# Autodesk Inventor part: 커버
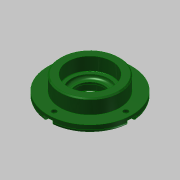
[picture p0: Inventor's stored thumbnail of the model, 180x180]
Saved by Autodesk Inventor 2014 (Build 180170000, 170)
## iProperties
Company: 한국ATC센터
Created: 2016-04
Part Number: 커버
Document SubType Name: Modeling
Designer: mdu
Density: 7.86 g/cm^3
Mass: 351.567 g
Surface Area: 161.165 cm^2
Volume: 44.7286 cm^3
Material: 강철, 연강
Appearance: 진녹색
Author: mdu
Revision Number: 1
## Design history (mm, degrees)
sketch "스케치1"
  geometry: C1 r 38 at (0, 0); 1 further point
  constraints: 1 centre point, 1 coincident
  dimensions: "d0" = 76 diameter of C1
extrude "돌출1" new body sketch "스케치1" distance "d1" = 7; taper "d2" = 0 deg
sketch "스케치2"
  geometry: C1 r 27 at (0, 0); 1 further point
  constraints: 1 centre point, 1 coincident
  dimensions: "d3" = 54 diameter of C1
extrude "돌출2" join sketch "스케치2" distance "d4" = 13; taper "d5" = 0 deg
sketch "스케치3"
  geometry: C1 r 20 at (0, 0); 1 further point
  constraints: 1 centre point, 1 coincident
  dimensions: "d6" = 40 diameter of C1
extrude "돌출3" join sketch "스케치3" distance "d7" = 5; taper "d8" = 0 deg
hole "구멍1" diameter "d11" = 25; stored, may be unused: countersink angle "d15" = 90 deg, drill point angle "d17" = 118 deg; dims "d9" = 10, "d10" = 10, "d12" = 6, "d13" = 32, "d14" = 8.3, "d16" = 8
hole "구멍2" diameter "d20" = 34; stored, may be unused: countersink angle "d24" = 90 deg, drill point angle "d26" = 0 deg; dims "d18" = 10, "d19" = 10, "d21" = 6, "d22" = 40, "d23" = 12, "d25" = 3
fillet "모깎기2" dims "d34" = 3
fillet "모깎기1" dims "d27" = 0.3
chamfer "모따기1" distance "d28" = 1; stored, may be unused: second distance "d29" = 2, angle "d30" = 45 deg
chamfer "모따기2" distance "d31" = 0.8; stored, may be unused: second distance "d32" = 2, angle "d33" = 30 deg
sketch "스케치4" dims "d35" = 65
  geometry: 3 further points
  constraints: 2 horizontal alignment, 1 coincident, 2 other
hole "구멍3" sketch "스케치4" at (32.5, 0) diameter "d36" = 4.5; stored, may be unused: countersink angle "d40" = 90 deg, drill point angle "d42" = 118 deg; dims "d37" = 6, "d38" = 8, "d39" = 4.4, "d41" = 13
sketch "스케치5"
  geometry: L1 (0, 4)-(5.5, 4); L2 (5.5, 4)-(5.5, -4); L3 (5.5, -4)-(0, -4); L4 (0, -4)-(0, 4); C1 r 2.25 at (0, 0) reference; C2 r 38 at (-32.5, 0) reference; 2 further points
  constraints: 8 end point, 3 horizontal, 2 parallel, 1 perpendicular, 1 tangent, 1 vertical alignment, 1 other
extrude "돌출4" cut sketch "스케치5" stored distance "d47" = 24.5; taper "d48" = 0 deg
node "솔리드1"
pattern_circular "원형 패턴1" dims angle "d44" = 360 deg
pattern_circular "원형 패턴2" dims angle "d50" = 360 deg
node "투영된 루프1"
